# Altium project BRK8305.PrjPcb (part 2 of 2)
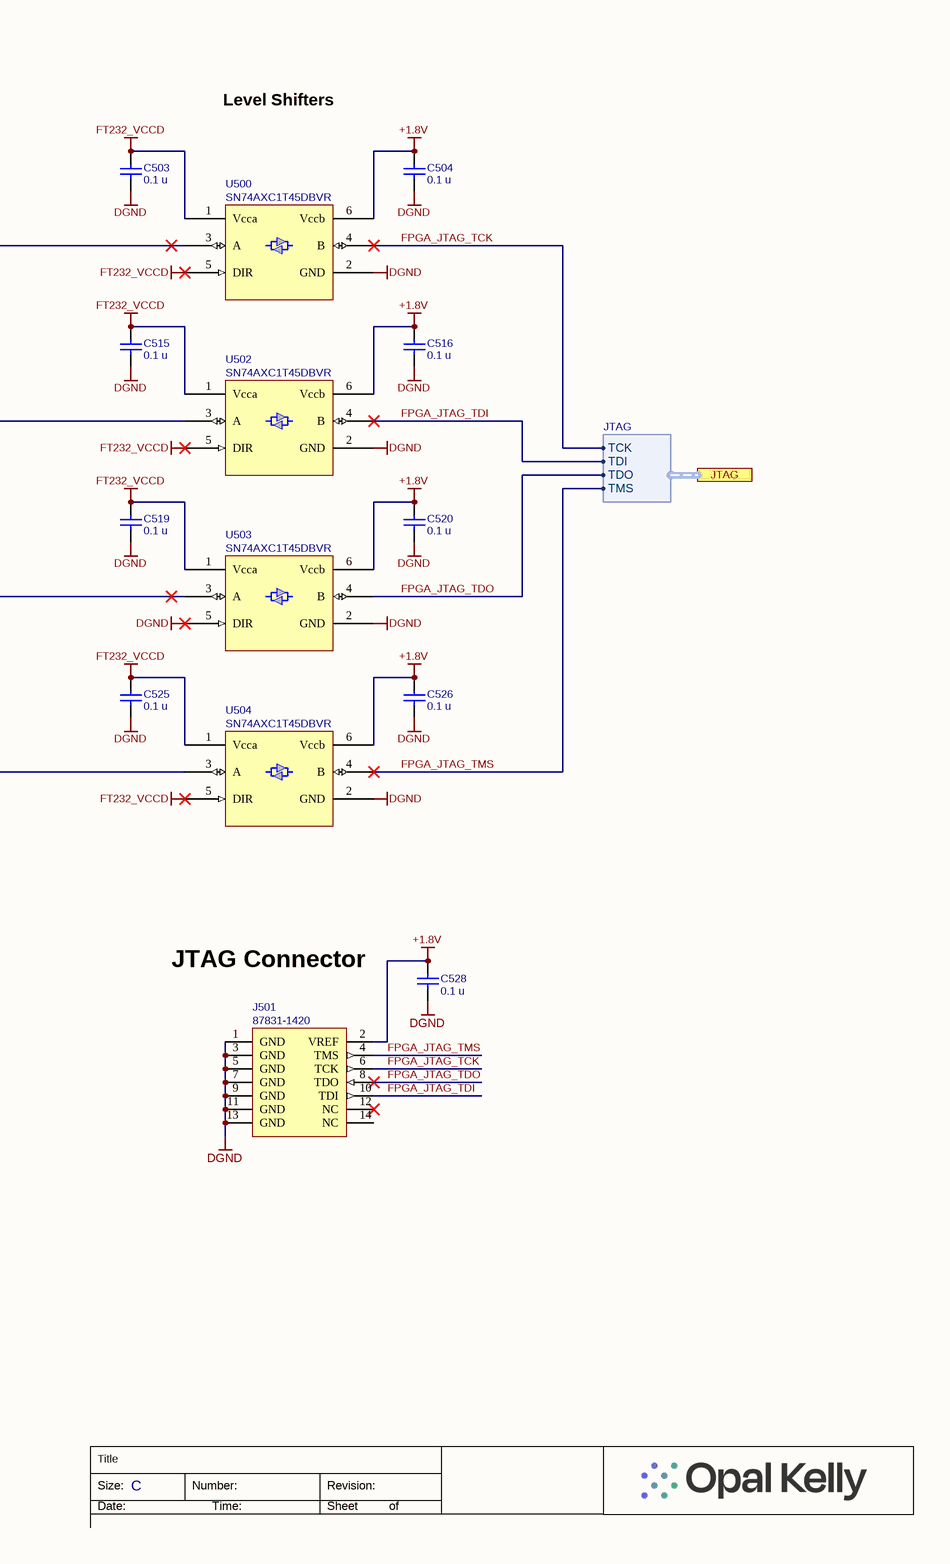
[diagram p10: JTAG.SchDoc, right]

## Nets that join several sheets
+1.8V: BRK8305 (9 pins), JTAG (10 pins)
+3.3V: BRK8305 (13 pins), PCIE (R30.2 R31.2), QSFP (14 pins)
DGND: BRK8305 (145 pins), PCIE (57 pins), QSFP (25 pins), JTAG (71 pins)
VCCO_85: BRK8305 (MC2.37 MC2.39 R35.2 TP23.1), PCIE (12 pins), QSFP (10 pins)
FPGA_JTAG_TCK: BRK8305 (MC2.1), JTAG (J501.6 U500.4)
FPGA_JTAG_TDI: BRK8305 (MC2.3), JTAG (J501.10 U502.4)
FPGA_JTAG_TDO: BRK8305 (MC2.7), JTAG (J501.8 U503.4)
FPGA_JTAG_TMS: BRK8305 (MC2.5), JTAG (J501.4 U504.4)
MGT_REFCLK0N_225_C: BRK8305 (MC3.54), PCIE (C8.2)
MGT_REFCLK0P_225_C: BRK8305 (MC3.52), PCIE (C7.2)
MGT_RXN0_224: BRK8305 (MC3.78), PCIE (J6.B46)
MGT_RXN0_225: BRK8305 (MC3.48), PCIE (J6.B28)
MGT_RXN0_226: BRK8305 (MC3.24), QSFP (J30.18)
MGT_RXN1_224: BRK8305 (MC3.72), PCIE (J6.B42)
MGT_RXN1_225: BRK8305 (MC3.42), PCIE (J6.B24)
MGT_RXN1_226: BRK8305 (MC3.18), QSFP (J30.21)
MGT_RXN2_224: BRK8305 (MC3.66), PCIE (J6.B38)
MGT_RXN2_225: BRK8305 (MC3.36), PCIE (J6.B20)
MGT_RXN2_226: BRK8305 (MC3.12), QSFP (J30.15)
MGT_RXN3_224: BRK8305 (MC3.60), PCIE (J6.B34)
MGT_RXN3_225: BRK8305 (MC3.30), PCIE (J6.B15)
MGT_RXN3_226: BRK8305 (MC3.6), QSFP (J30.24)
MGT_RXP0_224: BRK8305 (MC3.76), PCIE (J6.B45)
MGT_RXP0_225: BRK8305 (MC3.46), PCIE (J6.B27)
MGT_RXP0_226: BRK8305 (MC3.22), QSFP (J30.17)
MGT_RXP1_224: BRK8305 (MC3.70), PCIE (J6.B41)
MGT_RXP1_225: BRK8305 (MC3.40), PCIE (J6.B23)
MGT_RXP1_226: BRK8305 (MC3.16), QSFP (J30.22)
MGT_RXP2_224: BRK8305 (MC3.64), PCIE (J6.B37)
MGT_RXP2_225: BRK8305 (MC3.34), PCIE (J6.B19)
MGT_RXP2_226: BRK8305 (MC3.10), QSFP (J30.14)
MGT_RXP3_224: BRK8305 (MC3.58), PCIE (J6.B33)
MGT_RXP3_225: BRK8305 (MC3.28), PCIE (J6.B14)
MGT_RXP3_226: BRK8305 (MC3.4), QSFP (J30.25)
MGT_TXN0_224: BRK8305 (MC3.77), PCIE (C30.2)
MGT_TXN0_225: BRK8305 (MC3.47), PCIE (C20.2)
MGT_TXN0_226: BRK8305 (MC3.23), QSFP (J30.37)
MGT_TXN1_224: BRK8305 (MC3.71), PCIE (C26.2)
MGT_TXN1_225: BRK8305 (MC3.41), PCIE (C18.2)
MGT_TXN1_226: BRK8305 (MC3.17), QSFP (J30.2)
MGT_TXN2_224: BRK8305 (MC3.65), PCIE (C24.2)
MGT_TXN2_225: BRK8305 (MC3.35), PCIE (C16.2)
MGT_TXN2_226: BRK8305 (MC3.11), QSFP (J30.34)
MGT_TXN3_224: BRK8305 (MC3.59), PCIE (C22.2)
MGT_TXN3_225: BRK8305 (MC3.29), PCIE (C14.2)
MGT_TXN3_226: BRK8305 (MC3.5), QSFP (J30.5)
MGT_TXP0_224: BRK8305 (MC3.75), PCIE (C29.2)
MGT_TXP0_225: BRK8305 (MC3.45), PCIE (C19.2)
MGT_TXP0_226: BRK8305 (MC3.21), QSFP (J30.36)
MGT_TXP1_224: BRK8305 (MC3.69), PCIE (C25.2)
MGT_TXP1_225: BRK8305 (MC3.39), PCIE (C17.2)
MGT_TXP1_226: BRK8305 (MC3.15), QSFP (J30.3)
MGT_TXP2_224: BRK8305 (MC3.63), PCIE (C23.2)
MGT_TXP2_225: BRK8305 (MC3.33), PCIE (C15.2)
MGT_TXP2_226: BRK8305 (MC3.9), QSFP (J30.33)
MGT_TXP3_224: BRK8305 (MC3.57), PCIE (C21.2)
MGT_TXP3_225: BRK8305 (MC3.27), PCIE (C13.2)
MGT_TXP3_226: BRK8305 (MC3.3), QSFP (J30.6)
PCIE_PERST_B_VIO: BRK8305 (MC2.15), PCIE (R12.2 R20.1 TP13.1 U4.3)
PCIE_SMCLK_VIO: BRK8305 (MC2.11), PCIE (R14.1 TP12.1 U2.4)
PCIE_SMDAT_VIO: BRK8305 (MC2.13), PCIE (R15.1 TP9.1 U2.3)
PCIE_WAKE_B_VIO: BRK8305 (MC2.17), PCIE (R25.1 TP15.1 U6.3)
QSFP_INT_B_VIO: BRK8305 (MC2.19), QSFP (R49.1 U7.24)
QSFP_LP_MODE_VIO: BRK8305 (MC2.27), QSFP (R41.1 U7.4)
QSFP_MODPRS_B_VIO: BRK8305 (MC2.21), QSFP (R48.1 U7.1)
QSFP_MODSEL_B_VIO: BRK8305 (MC2.25), QSFP (R44.1 U7.3)
QSFP_RESET_B_VIO: BRK8305 (MC2.23), QSFP (R45.1 U7.2)
QSFP_SCL_VIO: BRK8305 (MC2.31), QSFP (R39.1 U7.6)
QSFP_SDA_VIO: BRK8305 (MC2.29), QSFP (R40.1 U7.5)

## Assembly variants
Default: not fitted C1 C2 C3 J2 J501 MC4 MC5 MC6 MC7 MC8 MC9 R5 R12 R16 R17 R20 R21 R22 R26 R27 R28 R43 R47 R75 R80 R504 R505 R506 U1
